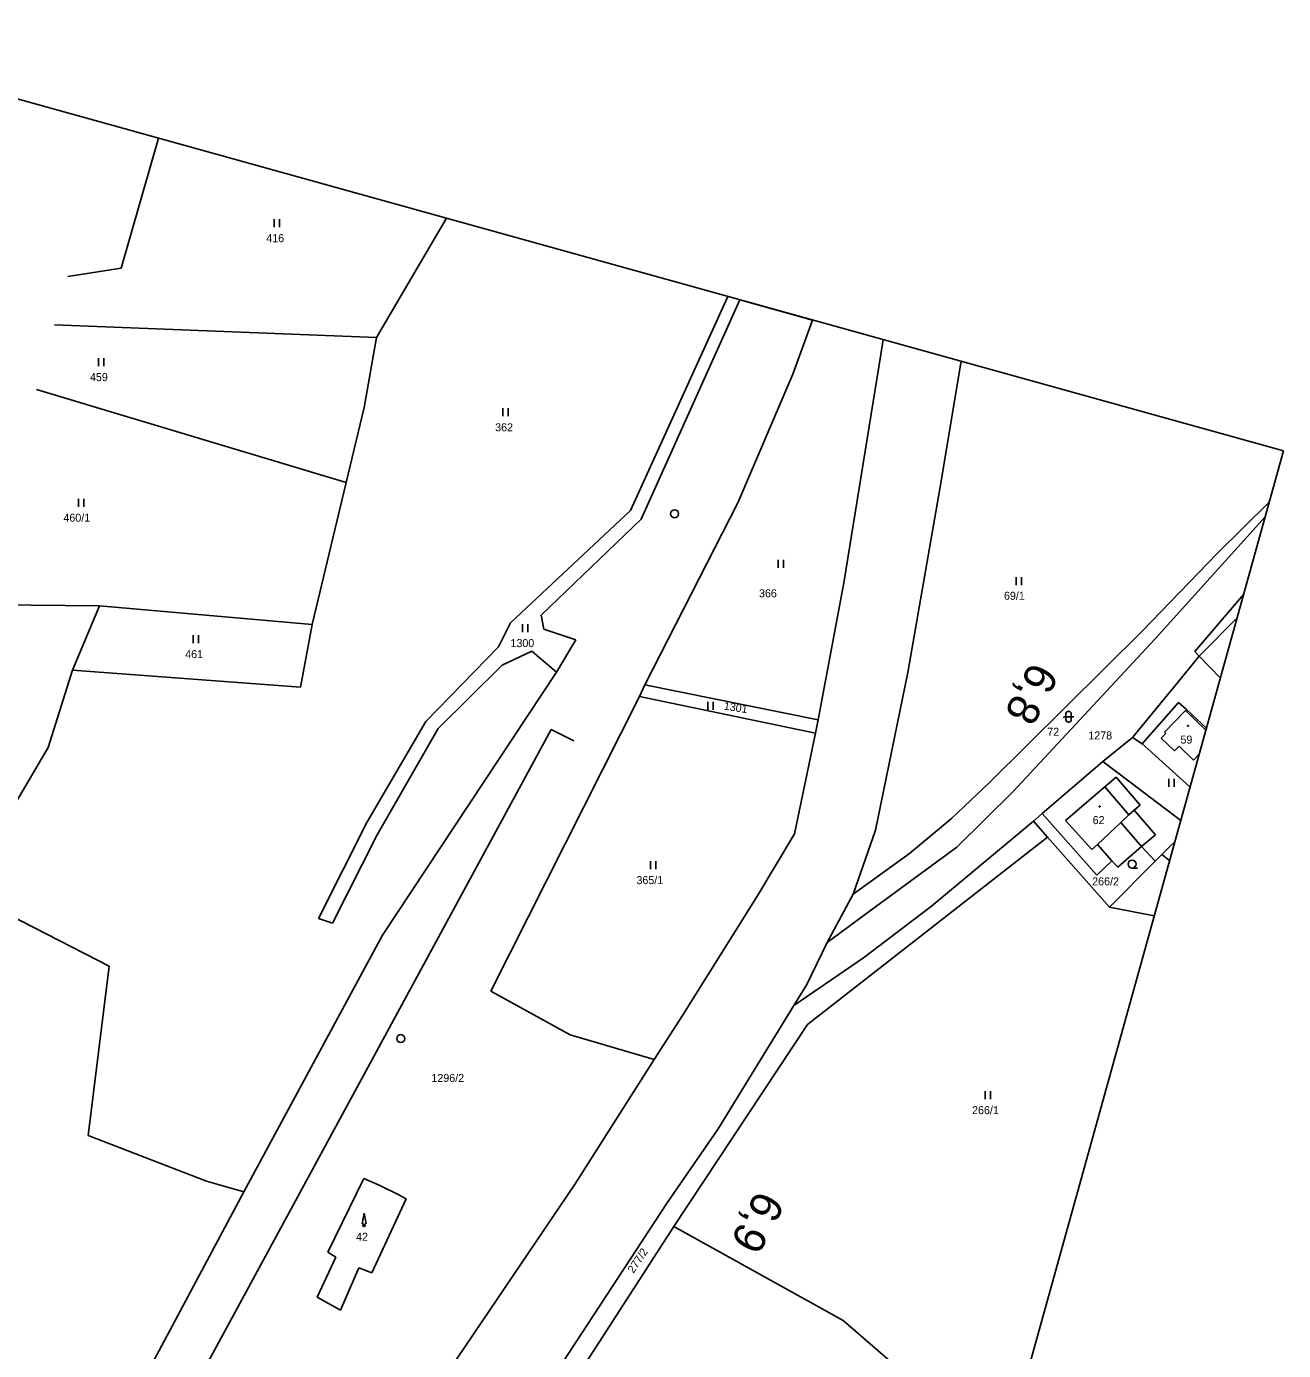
# Model space of a CAD drawing. Extents: x -795094 to -794639, y -1135368 to -1134681.
# Drawn here: x -794874.8 to -794639.2, y -1134929.4 to -1134681.2 of the extents above; entities that cross this region are included whole.
import ezdxf

# ---------------------------------------------------------------- set-up
doc = ezdxf.new("R2010")
doc.units = 0
for name, color, linetype in [('Default', 7, 'Continuous'), ('formát', 7, 'Continuous'), ('kilometráž - vrstava 7', 7, 'Continuous'), ('kn_celek - Cisla pozemkovych parcel', 7, 'Continuous'), ('kn_celek - Cisla stavebnich parcel', 7, 'Continuous'), ('kn_celek - Hranice parcel', 7, 'Continuous'), ('kn_celek - Vnitrni kresby', 7, 'Continuous'), ('kn_celek - Znacky budov', 7, 'Continuous'), ('kn_celek - Znacky kultur', 7, 'Continuous'), ('plochy - SZDC', 7, 'Continuous'), ('PSR_C2_1_trasa_Strunkovice - Kabelová trasa', 7, 'Continuous')]:
    doc.layers.add(name, color=color, linetype=linetype)

# ---------------------------------------------------------------- blocks, each defined once
blk = doc.blocks.new('319')
at = {"layer": 'Default'}
for p, q in [((-3.75, 2.5), (0, 22.5)), ((0, 22.5), (3.75, 2.5)), ((0, 2.5), (0, 0)), ((0, 2.5), (0, 0)), ((0, 0), (2.5, 0)), ((0, 0), (2.5, 0))]:
    blk.add_line(p, q, dxfattribs=at)
for start, end in [(90, 0), (0, 90), (0, 90)]:
    blk.add_arc((0, 0), 2.5, start, end, dxfattribs=at)
blk = doc.blocks.new('306')
at = {"layer": 'Default'}
for p, q in [((-5.2, 0), (-5.2, 15)), ((4.8, 0), (4.8, 15))]:
    blk.add_line(p, q, dxfattribs=at)
blk = doc.blocks.new('316')
at = {"layer": 'Default'}
for p, q in [((-8.3, 10), (-10, 8.1)), ((-5, 10), (-8.3, 10)), ((-5, 15.5), (-5, 4.5)), ((-5, 10), (5, 10)), ((0.5, 20), (-0.5, 20)), ((-0.5, 0), (0.5, 0)), ((5, 4.5), (5, 15.5)), ((10, 10), (5, 10))]:
    blk.add_line(p, q, dxfattribs=at)
for centre, start, end in [((-0.5, 15.5), 90, 180), ((-0.5, 4.5), 180, 270), ((0.5, 15.5), 0, 90), ((0.5, 4.5), 270, 0)]:
    blk.add_arc(centre, 4.5, start, end, dxfattribs=at)
blk = doc.blocks.new('304')
at = {"layer": 'Default'}
blk.add_line((-0.1, 0), (9.9, 0), dxfattribs=at)
blk.add_circle((-0.1, 7.5), 7.5, dxfattribs=at)
blk = doc.blocks.new('402')
at = {"layer": 'Default'}
for p, q in [((-0.8, 0.8), (0.7, 0.8)), ((-0.8, 0.8), (-0.8, -0.7)), ((0.7, 0.8), (0.7, -0.7)), ((0.7, -0.7), (-0.8, -0.7))]:
    blk.add_line(p, q, dxfattribs=at)

msp = doc.modelspace()

# ---------------------------------------------------------------- linework, layer by layer
at = {"layer": 'formát'}
for p, q in [((-794925.31, -1134681.22), (-794639.16, -1134760.77)), ((-794639.16, -1134760.77), (-794695.41, -1134963.1))]:
    msp.add_line(p, q, dxfattribs=at)
at = {"layer": 'kilometráž - vrstava 7'}
for centre in [(-794753.29, -1134772.54), (-794804.63, -1134870.91)]:
    msp.add_circle(centre, 0.75, dxfattribs=at)
at = {"layer": 'kn_celek - Hranice parcel'}
for p, q in [((-794850, -1134702.15), (-794857.03, -1134726.54)), ((-794796.04, -1134717.16), (-794809.19, -1134739.52)), ((-794857.03, -1134726.54), (-794867, -1134728.06)), ((-794743.29, -1134731.82), (-794761.54, -1134771.95)), ((-794741.05, -1134732.44), (-794759.53, -1134773.54)), ((-794727.43, -1134736.23), (-794731.15, -1134746.39)), ((-794869.52, -1134737.12), (-794809.19, -1134739.52)), ((-794809.19, -1134739.52), (-794811.49, -1134752.65)), ((-794714.65, -1134742.68), (-794714.19, -1134739.91)), ((-794721.59, -1134785.46), (-794714.65, -1134742.68)), ((-794703.59, -1134767.89), (-794699.59, -1134743.97)), ((-794731.15, -1134746.39), (-794741.45, -1134770.5)), ((-794872.9, -1134749.27), (-794814.87, -1134766.67)), ((-794811.49, -1134752.65), (-794814.87, -1134766.67)), ((-794814.87, -1134766.67), (-794821.21, -1134793.3)), ((-794709.56, -1134802.32), (-794703.59, -1134767.89)), ((-794741.45, -1134770.5), (-794758.9, -1134804.63)), ((-794651.57, -1134779.96), (-794641.84, -1134770.4)), ((-794761.54, -1134771.95), (-794784.08, -1134792.96)), ((-794759.53, -1134773.54), (-794778.33, -1134791.56)), ((-794642.59, -1134773.1), (-794663.25, -1134795.99)), ((-794651.57, -1134779.96), (-794665.58, -1134794.46)), ((-794726.41, -1134811.19), (-794721.59, -1134785.46)), ((-794646.62, -1134787.62), (-794655.76, -1134798.34)), ((-794884.1, -1134789.58), (-794861.07, -1134789.82)), ((-794861.07, -1134789.82), (-794866.17, -1134801.84)), ((-794821.21, -1134793.3), (-794861.07, -1134789.82)), ((-794778.33, -1134791.56), (-794777.82, -1134794.18)), ((-794823.4, -1134805.03), (-794821.21, -1134793.3)), ((-794784.08, -1134792.96), (-794786.32, -1134797.47)), ((-794647.86, -1134792.06), (-794654.95, -1134799.22)), ((-794777.82, -1134794.18), (-794771.78, -1134796.16)), ((-794771.78, -1134796.16), (-794775.44, -1134802.2)), ((-794694.29, -1134822.89), (-794665.58, -1134794.46)), ((-794689.83, -1134824.61), (-794663.25, -1134795.99)), ((-794786.32, -1134797.47), (-794799.95, -1134811.47)), ((-794785.61, -1134800.9), (-794780.03, -1134798.3)), ((-794780.03, -1134798.3), (-794775.44, -1134802.2)), ((-794654.95, -1134799.22), (-794655.76, -1134798.34)), ((-794797.58, -1134812.81), (-794785.61, -1134800.9)), ((-794659.94, -1134805.37), (-794654.95, -1134799.22)), ((-794651, -1134803.34), (-794654.95, -1134799.22)), ((-794866.17, -1134801.84), (-794870.71, -1134816.38)), ((-794866.17, -1134801.84), (-794823.4, -1134805.03)), ((-794775.44, -1134802.2), (-794808.02, -1134851.51)), ((-794715.61, -1134831.85), (-794709.56, -1134802.32)), ((-794758.9, -1134804.63), (-794759.9, -1134806.76)), ((-794758.9, -1134804.63), (-794726.41, -1134811.19)), ((-794667.45, -1134814.45), (-794659.94, -1134805.37)), ((-794759.9, -1134806.76), (-794787.72, -1134861.99)), ((-794759.9, -1134806.76), (-794726.91, -1134813.66)), ((-794665.63, -1134815.65), (-794658.84, -1134807.9)), ((-794658.84, -1134807.9), (-794657.33, -1134809.22)), ((-794726.91, -1134813.66), (-794726.41, -1134811.19)), ((-794653.61, -1134812.75), (-794657.33, -1134809.22)), ((-794799.95, -1134811.47), (-794810.99, -1134830.43)), ((-794809.07, -1134832.69), (-794797.58, -1134812.81)), ((-794730.84, -1134832.54), (-794726.91, -1134813.66)), ((-794870.71, -1134816.38), (-794886.61, -1134843.34)), ((-794673, -1134818.95), (-794667.45, -1134814.45)), ((-794667.45, -1134814.45), (-794665.63, -1134815.65)), ((-794665.63, -1134815.65), (-794664.5, -1134816.64)), ((-794664.5, -1134816.64), (-794656.68, -1134823.8)), ((-794684.4, -1134828.72), (-794673, -1134818.95)), ((-794673, -1134818.95), (-794658.42, -1134830.06)), ((-794701.41, -1134829.66), (-794694.29, -1134822.89)), ((-794700.4, -1134835.03), (-794689.83, -1134824.61)), ((-794686.02, -1134830.15), (-794684.4, -1134828.72)), ((-794684.4, -1134828.72), (-794674.15, -1134840.25)), ((-794810.99, -1134830.43), (-794820.06, -1134848.39)), ((-794709.29, -1134836.19), (-794701.41, -1134829.66)), ((-794705.12, -1134846.08), (-794686.02, -1134830.15)), ((-794683.38, -1134833.15), (-794686.02, -1134830.15)), ((-794817.42, -1134849.28), (-794809.07, -1134832.69)), ((-794737.72, -1134844.03), (-794730.84, -1134832.54)), ((-794683.38, -1134833.15), (-794728.39, -1134868.27)), ((-794719.8, -1134843.86), (-794715.61, -1134831.85)), ((-794671.8, -1134846.3), (-794683.38, -1134833.15)), ((-794719.8, -1134843.86), (-794709.29, -1134836.19)), ((-794715.61, -1134846.22), (-794700.4, -1134835.03)), ((-794665.75, -1134834.91), (-794670.23, -1134838.78)), ((-794663.24, -1134837.68), (-794665.75, -1134834.91)), ((-794661.94, -1134836.38), (-794660.82, -1134835.26)), ((-794660.82, -1134835.26), (-794659.5, -1134833.94)), ((-794674.15, -1134840.25), (-794671.31, -1134837.56)), ((-794663.24, -1134837.68), (-794671.8, -1134846.3)), ((-794670.23, -1134838.78), (-794671.31, -1134837.56)), ((-794661.94, -1134836.38), (-794663.24, -1134837.68)), ((-794661.94, -1134836.38), (-794660.51, -1134837.54)), ((-794886.61, -1134843.34), (-794859.28, -1134857.32)), ((-794751.82, -1134866.58), (-794737.72, -1134844.03)), ((-794724.67, -1134852.88), (-794719.8, -1134843.86)), ((-794717.86, -1134855.74), (-794705.12, -1134846.08)), ((-794820.06, -1134848.39), (-794817.42, -1134849.28)), ((-794724.67, -1134852.88), (-794715.61, -1134846.22)), ((-794671.8, -1134846.3), (-794663.38, -1134847.87)), ((-794808.02, -1134851.51), (-794834.03, -1134899.62)), ((-794728.48, -1134860.75), (-794724.67, -1134852.88)), ((-794730.92, -1134864.71), (-794717.86, -1134855.74)), ((-794859.28, -1134857.32), (-794863.22, -1134889.04)), ((-794730.92, -1134864.71), (-794728.48, -1134860.75)), ((-794787.72, -1134861.99), (-794772.84, -1134870.22)), ((-794745.13, -1134887.82), (-794730.92, -1134864.71)), ((-794757.13, -1134874.85), (-794751.82, -1134866.58)), ((-794728.39, -1134868.27), (-794753.41, -1134906.1)), ((-794772.84, -1134870.22), (-794757.13, -1134874.85)), ((-794771.93, -1134898.11), (-794757.13, -1134874.85)), ((-794754.68, -1134901.67), (-794745.13, -1134887.82)), ((-794863.22, -1134889.04), (-794841.05, -1134897.6)), ((-794841.05, -1134897.6), (-794834.03, -1134899.62)), ((-794811.52, -1134897.15), (-794818.27, -1134910.96)), ((-794808.67, -1134898.39), (-794811.52, -1134897.15)), ((-794808.62, -1134952.39), (-794771.93, -1134898.11)), ((-794834.03, -1134899.62), (-794854.06, -1134937.12)), ((-794805, -1134900.19), (-794808.67, -1134898.39)), ((-794803.6, -1134900.93), (-794805, -1134900.19)), ((-794810.05, -1134914.8), (-794803.6, -1134900.93)), ((-794777.33, -1134936.24), (-794754.68, -1134901.67)), ((-794753.41, -1134906.1), (-794771.9, -1134934.67)), ((-794753.41, -1134906.1), (-794721.7, -1134923.76)), ((-794816.8, -1134911.86), (-794820.3, -1134919.39)), ((-794818.27, -1134910.96), (-794816.8, -1134911.86)), ((-794815.9, -1134921.79), (-794812.5, -1134913.85)), ((-794812.5, -1134913.85), (-794810.05, -1134914.8)), ((-794820.3, -1134919.39), (-794815.9, -1134921.79)), ((-794721.7, -1134923.76), (-794699.33, -1134943.07))]:
    msp.add_line(p, q, dxfattribs=at)
at = {"layer": 'kn_celek - Vnitrni kresby'}
for p, q in [((-794657.54, -1134809.44), (-794661.46, -1134813.49)), ((-794653.72, -1134813.13), (-794657.54, -1134809.44)), ((-794661.24, -1134813.7), (-794662.08, -1134814.57)), ((-794661.46, -1134813.49), (-794661.24, -1134813.7)), ((-794662.08, -1134814.57), (-794659.58, -1134816.98)), ((-794659.58, -1134816.98), (-794658.74, -1134816.11)), ((-794658.74, -1134816.11), (-794656.06, -1134818.7)), ((-794656.06, -1134818.7), (-794654.94, -1134817.52)), ((-794672.68, -1134823.75), (-794680.04, -1134830.06)), ((-794672.68, -1134823.75), (-794670.56, -1134821.93)), ((-794672.68, -1134823.75), (-794668.13, -1134828.96)), ((-794670.56, -1134821.93), (-794666.05, -1134827.15)), ((-794668.13, -1134828.96), (-794667.14, -1134828.1)), ((-794666.05, -1134827.15), (-794667.14, -1134828.1)), ((-794667.14, -1134828.1), (-794663.18, -1134832.69)), ((-794675.07, -1134835.44), (-794680.04, -1134830.06)), ((-794669.66, -1134830.39), (-794674.01, -1134834.51)), ((-794668.13, -1134828.96), (-794669.66, -1134830.39)), ((-794665.75, -1134834.91), (-794669.66, -1134830.39)), ((-794663.18, -1134832.69), (-794665.75, -1134834.91)), ((-794674.01, -1134834.51), (-794675.07, -1134835.44)), ((-794671.31, -1134837.56), (-794674.01, -1134834.51))]:
    msp.add_line(p, q, dxfattribs=at)
at = {"layer": 'plochy - SZDC'}
for p, q in [((-794741.05, -1134732.44), (-794759.53, -1134773.54)), ((-794727.43, -1134736.23), (-794741.05, -1134732.44)), ((-794731.15, -1134746.39), (-794727.43, -1134736.23)), ((-794741.45, -1134770.5), (-794731.15, -1134746.39)), ((-794758.9, -1134804.63), (-794741.45, -1134770.5)), ((-794759.53, -1134773.54), (-794778.33, -1134791.56)), ((-794778.33, -1134791.56), (-794777.82, -1134794.18)), ((-794777.82, -1134794.18), (-794771.78, -1134796.16)), ((-794771.78, -1134796.16), (-794775.44, -1134802.2)), ((-794775.44, -1134802.2), (-794808.02, -1134851.51)), ((-794759.9, -1134806.76), (-794758.9, -1134804.63)), ((-794787.72, -1134861.99), (-794759.9, -1134806.76)), ((-794808.02, -1134851.51), (-794834.03, -1134899.62)), ((-794772.84, -1134870.22), (-794787.72, -1134861.99)), ((-794757.13, -1134874.85), (-794772.84, -1134870.22)), ((-794771.93, -1134898.11), (-794757.13, -1134874.85)), ((-794818.27, -1134910.96), (-794811.52, -1134897.15)), ((-794811.52, -1134897.15), (-794808.67, -1134898.39)), ((-794808.62, -1134952.39), (-794771.93, -1134898.11)), ((-794834.03, -1134899.62), (-794854.06, -1134937.12)), ((-794808.67, -1134898.39), (-794805, -1134900.19)), ((-794805, -1134900.19), (-794803.6, -1134900.93)), ((-794803.6, -1134900.93), (-794810.05, -1134914.8)), ((-794820.3, -1134919.39), (-794816.8, -1134911.86)), ((-794816.8, -1134911.86), (-794818.27, -1134910.96)), ((-794812.5, -1134913.85), (-794815.9, -1134921.79)), ((-794810.05, -1134914.8), (-794812.5, -1134913.85)), ((-794815.9, -1134921.79), (-794820.3, -1134919.39))]:
    msp.add_line(p, q, dxfattribs=at)
at = {"layer": 'PSR_C2_1_trasa_Strunkovice - Kabelová trasa'}
msp.add_lwpolyline([(-794859.57, -1134988.66), (-794835.3, -1134945.55), (-794845.51, -1134940.37), (-794776.44, -1134813), (-794772.18, -1134815.08)], dxfattribs=at)

# ---------------------------------------------------------------- block references
at = {"layer": 'kn_celek - Znacky budov', "xscale": 0.1, "yscale": 0.10000000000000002}
for p in [(-794657.05, -1134812.28), (-794673.62, -1134827.42)]:
    msp.add_blockref('402', p, dxfattribs=at)
at = {"layer": 'kn_celek - Znacky kultur', "xscale": 0.1, "yscale": 0.10000000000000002}
for name, p in [('306', (-794827.86, -1134718.83)), ('306', (-794860.76, -1134744.88)), ('306', (-794784.96, -1134754.25)), ('306', (-794864.51, -1134771.23)), ('306', (-794733.39, -1134782.68)), ('306', (-794688.76, -1134785.91)), ('306', (-794781.31, -1134794.76)), ('306', (-794843, -1134796.8)), ('306', (-794746.53, -1134809.3)), ('316', (-794679.44, -1134811.58)), ('306', (-794660.16, -1134823.7)), ('306', (-794757.32, -1134839.16)), ('304', (-794667.54, -1134838.95)), ('306', (-794694.56, -1134882.27)), ('319', (-794811.51, -1134905.9))]:
    msp.add_blockref(name, p, dxfattribs=at)

# ---------------------------------------------------------------- texts
at = {"layer": 'kilometráž - vrstava 7'}
for s, rotation, p in [('6,8', 242.6352, (-794686.43, -1134800.02)), ('6,9', 242.3222, (-794737.76, -1134899.06))]:
    msp.add_text(s, height=6, rotation=rotation, dxfattribs=at).set_placement(p)
at = {"layer": 'kn_celek - Cisla pozemkovych parcel'}
for s, p in [('416', (-794829.83, -1134721.64)), ('459', (-794862.87, -1134747.68)), ('362', (-794786.93, -1134757.09)), ('460/1', (-794867.85, -1134774.03)), ('366', (-794737.48, -1134788.2)), ('69/1', (-794691.56, -1134788.66)), ('1300', (-794784.06, -1134797.53)), ('461', (-794845.03, -1134799.6)), ('72', (-794683.44, -1134814.15)), ('1278', (-794675.75, -1134814.84)), ('365/1', (-794760.45, -1134841.96)), ('266/2', (-794675.03, -1134842.19)), ('1296/2', (-794798.88, -1134879.03)), ('266/1', (-794697.54, -1134885.07))]:
    msp.add_text(s, height=1.5, dxfattribs=at).set_placement(p)
for s, rotation, p in [('1301', 351.2283, (-794744.15, -1134809.24)), ('277/2', 56.3099, (-794760.99, -1134915.01))]:
    msp.add_text(s, height=1.5, rotation=rotation, dxfattribs=at).set_placement(p)
at = {"layer": 'kn_celek - Cisla stavebnich parcel'}
for s, p in [('59', (-794658.48, -1134815.62)), ('62', (-794674.94, -1134830.71)), ('42', (-794813, -1134908.8))]:
    msp.add_text(s, height=1.5, dxfattribs=at).set_placement(p)

doc.saveas('drawing.dxf')
